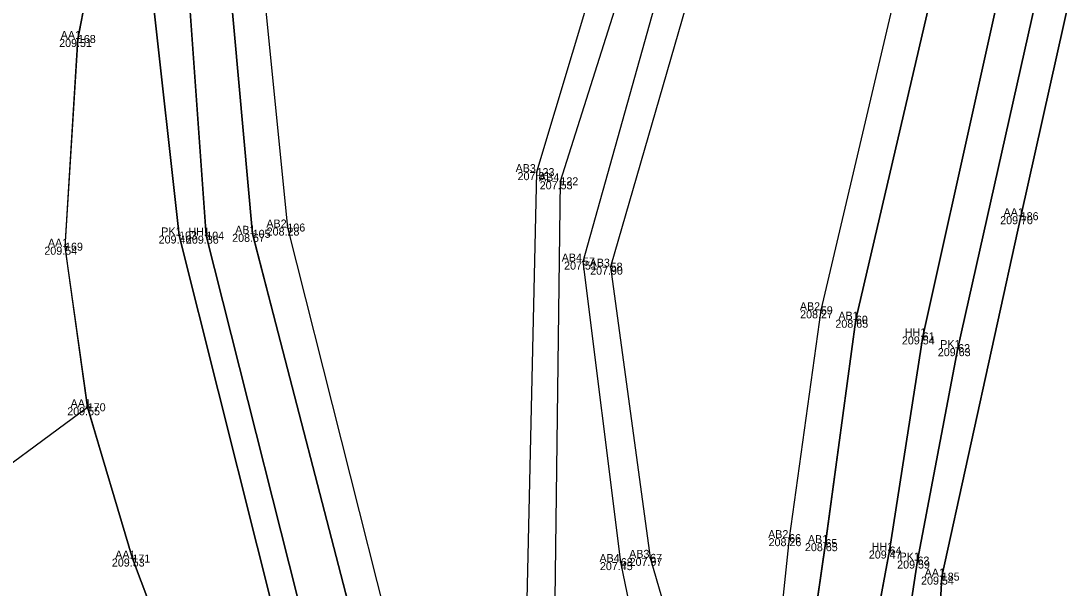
# Model space of a CAD drawing. Extents: x -263091 to -262565, y -1238731 to -1237092.
# Drawn here: x -262957.98 to -262931.8, y -1238381.51 to -1238367.34 of the extents above; entities that cross this region are included whole.
import ezdxf

# ---------------------------------------------------------------- set-up
doc = ezdxf.new("R2010")
doc.units = 0
for name, color, linetype in [('01_Hrana_betónu', 7, 'Continuous'), ('02_Oplotenie', 7, 'Continuous'), ('03_Asfalt', 7, 'Continuous'), ('05_Hrana_terénu', 7, 'Continuous'), ('Groma (21)', 7, 'Continuous'), ('Groma (22)', 7, 'Continuous'), ('Groma (23)', 7, 'Continuous'), ('Groma (24)', 7, 'Continuous'), ('U002_Asfalt', 7, 'Continuous'), ('U002_Betónové panely', 7, 'Continuous'), ('U002_Zeleň_mimo', 7, 'Continuous'), ('U002_Zeleň_vnútro', 7, 'Continuous'), ('U002_Zeleň_zatrávňovač', 7, 'Continuous')]:
    doc.layers.add(name, color=color, linetype=linetype)

msp = doc.modelspace()

# ---------------------------------------------------------------- linework, layer by layer
at = {"layer": '01_Hrana_betónu'}
for points in [[(-262944.213, -1238387.387), (-262944.634, -1238381.789), (-262944.5, -1238371.343), (-262941.2, -1238360.927), (-262935.086, -1238341.218), (-262927.632, -1238317.179), (-262920.793, -1238295.265), (-262911.171, -1238262.813), (-262915.352, -1238261.064), (-262915.337, -1238259.329), (-262909.866, -1238261.629), (-262904.904, -1238263.716)], [(-262916.095, -1238261.519), (-262911.974, -1238263.293), (-262921.591, -1238294.909), (-262928.534, -1238317.073), (-262935.896, -1238340.99), (-262941.971, -1238360.685), (-262945.096, -1238371.115), (-262945.34, -1238381.803), (-262945.412, -1238387.557)], [(-262941.714, -1238387.032), (-262942.991, -1238380.859), (-262943.934, -1238373.35), (-262940.485, -1238361.041), (-262934.456, -1238341.421), (-262927.277, -1238318.134), (-262920.116, -1238294.802), (-262913.64, -1238273.614), (-262910.214, -1238263.245), (-262905.769, -1238265.099), (-262904.904, -1238263.716)], [(-262905.769, -1238265.099), (-262909.81, -1238264.181), (-262912.956, -1238273.861), (-262919.396, -1238295.066), (-262926.538, -1238318.409), (-262933.693, -1238341.579), (-262939.683, -1238361.151), (-262943.246, -1238373.477), (-262942.259, -1238380.752), (-262940.526, -1238386.713)], [(-262905.769, -1238265.099), (-262909.014, -1238275.12), (-262915.393, -1238296.189), (-262922.597, -1238319.497), (-262929.796, -1238342.936), (-262935.083, -1238362.17), (-262937.995, -1238374.567), (-262938.788, -1238380.26), (-262939.46, -1238386.668), (-262940.526, -1238386.713), (-262940.498, -1238386.859)], [(-262940.36, -1238387.407), (-262939.388, -1238387.391), (-262938.822, -1238386.902), (-262937.88, -1238380.385), (-262937.119, -1238374.802), (-262934.23, -1238362.39), (-262928.952, -1238343.2), (-262921.717, -1238319.813), (-262915.107, -1238298.192), (-262908.208, -1238275.423), (-262904.855, -1238265.436)], [(-262945.333, -1238387.95), (-262946.617, -1238387.98), (-262947.712, -1238387.066), (-262949.402, -1238383.422), (-262952.187, -1238372.656), (-262952.759, -1238366.382)], [(-262951.91, -1238366.581), (-262951.321, -1238372.499), (-262948.634, -1238383.126), (-262947.098, -1238386.578), (-262946.426, -1238387.428), (-262945.412, -1238387.557)]]:
    msp.add_lwpolyline(points, dxfattribs=at)
at = {"layer": '02_Oplotenie'}
msp.add_lwpolyline([(-262939.39, -1238320.83), (-262941.19, -1238324.79), (-262946.68, -1238336.9), (-262951.035, -1238350.68), (-262953.195, -1238358.97), (-262953.815, -1238358.809), (-262955.312, -1238364.513), (-262954.553, -1238364.724), (-262954.681, -1238366.785), (-262954.024, -1238372.698), (-262951.104, -1238384.342), (-262949.016, -1238390.045), (-262944.443, -1238389.969), (-262936.906, -1238389.616), (-262935.581, -1238380.82), (-262934.566, -1238375.513), (-262931.812, -1238363.194), (-262926.159, -1238344.076), (-262918.903, -1238320.384), (-262912.242, -1238298.942), (-262905.326, -1238276.054), (-262902.598, -1238266.292), (-262902.107, -1238264.892)], dxfattribs=at)
at = {"layer": '03_Asfalt'}
msp.add_lwpolyline([(-262931.199, -1238364.162), (-262933.003, -1238372.216), (-262934.974, -1238381.221), (-262935.119, -1238384.027), (-262936.052, -1238388.803), (-262936.611, -1238390.144), (-262937.981, -1238391.744), (-262940.017, -1238393.235), (-262941.857, -1238393.766), (-262943.351, -1238393.675), (-262945.246, -1238393.033), (-262947.034, -1238391.969), (-262949.331, -1238390.232), (-262950.782, -1238388.665), (-262952.605, -1238386.269), (-262954.108, -1238383.642), (-262955.193, -1238380.77), (-262956.307, -1238376.99), (-262956.874, -1238372.978), (-262956.554, -1238367.788), (-262955.999, -1238364.917)], dxfattribs=at)
at = {"layer": '05_Hrana_terénu'}
msp.add_lwpolyline([(-262920.126, -1238320.151), (-262927.385, -1238343.686), (-262932.704, -1238362.854), (-262935.453, -1238375.219), (-262936.279, -1238380.57), (-262937.519, -1238387.253), (-262938.314, -1238388.733), (-262939.759, -1238389.403), (-262945.681, -1238389.45), (-262947.587, -1238388.865), (-262949.049, -1238387.288), (-262950.436, -1238384.21), (-262953.347, -1238372.702), (-262953.777, -1238366.63), (-262954.163, -1238366.041), (-262952.487, -1238358.01), (-262951.855, -1238357.25), (-262949.897, -1238349.853), (-262950.29, -1238348.92), (-262949.45, -1238345.83), (-262948.76, -1238345.496), (-262946.63, -1238339.15), (-262945.04, -1238334.12), (-262941.75, -1238326.63)], dxfattribs=at)
at = {"layer": 'Groma (21)'}
for centre in [(-262956.554, -1238367.788), (-262945.096, -1238371.115), (-262944.5, -1238371.343), (-262933.003, -1238372.216), (-262952.187, -1238372.656), (-262951.321, -1238372.499), (-262954.024, -1238372.698), (-262953.347, -1238372.702), (-262956.874, -1238372.978), (-262943.934, -1238373.35), (-262943.246, -1238373.477), (-262937.995, -1238374.567), (-262937.119, -1238374.802), (-262935.453, -1238375.219), (-262934.566, -1238375.513), (-262956.307, -1238376.99), (-262938.788, -1238380.26), (-262937.88, -1238380.385), (-262955.193, -1238380.77), (-262942.259, -1238380.752), (-262936.279, -1238380.57), (-262942.991, -1238380.859), (-262935.581, -1238380.82), (-262934.974, -1238381.221)]:
    msp.add_circle(centre, 0.01, dxfattribs=at)
at = {"layer": 'U002_Asfalt'}
msp.add_lwpolyline([(-262962.63, -1238381.65), (-262956.31, -1238376.99), (-262955.19, -1238380.77), (-262954.11, -1238383.64), (-262952.61, -1238386.27), (-262950.78, -1238388.67), (-262949.33, -1238390.23), (-262947.03, -1238391.97), (-262945.25, -1238393.03), (-262943.35, -1238393.68), (-262941.86, -1238393.77), (-262940.02, -1238393.24), (-262937.98, -1238391.74), (-262936.61, -1238390.14), (-262936.05, -1238388.8), (-262935.12, -1238384.03), (-262934.97, -1238381.22), (-262933, -1238372.22), (-262931.2, -1238364.16)], dxfattribs=at)
msp.add_lwpolyline([(-262962.63, -1238381.65), (-262956.31, -1238376.99), (-262955.19, -1238380.77), (-262954.11, -1238383.64), (-262952.61, -1238386.27), (-262950.78, -1238388.67), (-262949.33, -1238390.23), (-262947.03, -1238391.97), (-262945.25, -1238393.03), (-262943.35, -1238393.68), (-262941.86, -1238393.77), (-262940.02, -1238393.24), (-262937.98, -1238391.74), (-262936.61, -1238390.14), (-262936.05, -1238388.8), (-262935.12, -1238384.03), (-262934.97, -1238381.22), (-262933, -1238372.22), (-262931.2, -1238364.16)], dxfattribs=at)
at = {"layer": 'U002_Betónové panely'}
msp.add_lwpolyline([(-262934.23, -1238362.39), (-262937.12, -1238374.8), (-262937.88, -1238380.39), (-262938.82, -1238386.9), (-262939.39, -1238387.39), (-262940.36, -1238387.41), (-262940.41, -1238387.31), (-262940.5, -1238386.86), (-262941.71, -1238387.03), (-262944.21, -1238387.39), (-262945.41, -1238387.56), (-262945.33, -1238387.95), (-262946.62, -1238387.98), (-262947.71, -1238387.07), (-262949.4, -1238383.42), (-262952.19, -1238372.66), (-262952.76, -1238366.38)], dxfattribs=at)
msp.add_lwpolyline([(-262934.23, -1238362.39), (-262937.12, -1238374.8), (-262937.88, -1238380.39), (-262938.82, -1238386.9), (-262939.39, -1238387.39), (-262940.36, -1238387.41), (-262940.41, -1238387.31), (-262940.5, -1238386.86), (-262941.71, -1238387.03), (-262944.21, -1238387.39), (-262945.41, -1238387.56), (-262945.33, -1238387.95), (-262946.62, -1238387.98), (-262947.71, -1238387.07), (-262949.4, -1238383.42), (-262952.19, -1238372.66), (-262952.76, -1238366.38)], dxfattribs=at)
at = {"layer": 'U002_Zeleň_mimo'}
for points in [[(-262954.68, -1238366.78), (-262954.02, -1238372.7), (-262951.1, -1238384.34), (-262949.02, -1238390.05), (-262944.44, -1238389.97), (-262936.91, -1238389.62), (-262935.58, -1238380.82), (-262934.57, -1238375.51), (-262931.81, -1238363.19)], [(-262931.2, -1238364.16), (-262933, -1238372.22), (-262934.97, -1238381.22), (-262935.12, -1238384.03), (-262936.05, -1238388.8), (-262936.61, -1238390.14), (-262937.98, -1238391.74), (-262940.02, -1238393.24), (-262941.86, -1238393.77), (-262943.35, -1238393.68), (-262945.25, -1238393.03), (-262947.03, -1238391.97), (-262949.33, -1238390.23), (-262950.78, -1238388.67), (-262952.61, -1238386.27), (-262954.11, -1238383.64), (-262955.19, -1238380.77), (-262956.31, -1238376.99), (-262956.87, -1238372.98), (-262956.55, -1238367.79), (-262956, -1238364.92)]]:
    msp.add_lwpolyline(points, dxfattribs=at)
at = {"layer": 'U002_Zeleň_vnútro'}
for points in [[(-262918.9, -1238320.38), (-262926.16, -1238344.08), (-262931.81, -1238363.19), (-262934.57, -1238375.51), (-262935.58, -1238380.82), (-262936.91, -1238389.62), (-262944.44, -1238389.97), (-262949.02, -1238390.05), (-262951.1, -1238384.34), (-262954.02, -1238372.7), (-262954.68, -1238366.78), (-262954.55, -1238364.72), (-262955.31, -1238364.51), (-262953.82, -1238358.81), (-262953.2, -1238358.97), (-262951.03, -1238350.68), (-262946.68, -1238336.9), (-262941.19, -1238324.79)], [(-262918.9, -1238320.38), (-262926.16, -1238344.08), (-262931.81, -1238363.19), (-262934.57, -1238375.51), (-262935.58, -1238380.82), (-262936.91, -1238389.62), (-262944.44, -1238389.97), (-262949.02, -1238390.05)], [(-262949.02, -1238390.05), (-262951.1, -1238384.34), (-262954.02, -1238372.7), (-262954.68, -1238366.78), (-262954.55, -1238364.72), (-262955.31, -1238364.51), (-262953.82, -1238358.81), (-262953.2, -1238358.97), (-262951.03, -1238350.68), (-262946.68, -1238336.9), (-262941.19, -1238324.79)], [(-262953.78, -1238366.63), (-262953.35, -1238372.7), (-262950.44, -1238384.21), (-262949.05, -1238387.29), (-262947.59, -1238388.87), (-262945.68, -1238389.45), (-262939.76, -1238389.4), (-262938.31, -1238388.73), (-262937.52, -1238387.25), (-262936.28, -1238380.57), (-262935.45, -1238375.22), (-262932.7, -1238362.85)], [(-262953.78, -1238366.63), (-262953.35, -1238372.7), (-262950.44, -1238384.21), (-262949.05, -1238387.29), (-262947.59, -1238388.87), (-262945.68, -1238389.45), (-262939.76, -1238389.4), (-262938.31, -1238388.73), (-262937.52, -1238387.25), (-262936.28, -1238380.57), (-262935.45, -1238375.22), (-262932.7, -1238362.85)]]:
    msp.add_lwpolyline(points, dxfattribs=at)
at = {"layer": 'U002_Zeleň_zatrávňovač'}
for points in [[(-262945.68, -1238389.45), (-262947.59, -1238388.87), (-262949.05, -1238387.29), (-262950.44, -1238384.21), (-262953.35, -1238372.7), (-262953.78, -1238366.63), (-262954.16, -1238366.04), (-262952.76, -1238366.38), (-262952.19, -1238372.66), (-262949.4, -1238383.42), (-262947.71, -1238387.07), (-262946.62, -1238387.98), (-262945.33, -1238387.95), (-262940.41, -1238387.31), (-262940.36, -1238387.41), (-262939.39, -1238387.39), (-262938.82, -1238386.9), (-262937.88, -1238380.39), (-262937.12, -1238374.8), (-262934.23, -1238362.39), (-262928.95, -1238343.2), (-262921.72, -1238319.81)], [(-262920.13, -1238320.15), (-262927.39, -1238343.69), (-262932.7, -1238362.85), (-262935.45, -1238375.22), (-262936.28, -1238380.57), (-262937.52, -1238387.25), (-262938.31, -1238388.73), (-262939.76, -1238389.4), (-262945.68, -1238389.45)], [(-262952.76, -1238366.38), (-262952.19, -1238372.66), (-262949.4, -1238383.42), (-262947.71, -1238387.07), (-262946.62, -1238387.98), (-262945.33, -1238387.95), (-262940.41, -1238387.31), (-262940.36, -1238387.41), (-262939.39, -1238387.39), (-262938.82, -1238386.9), (-262937.88, -1238380.39), (-262937.12, -1238374.8), (-262934.23, -1238362.39)], [(-262932.7, -1238362.85), (-262935.45, -1238375.22), (-262936.28, -1238380.57), (-262937.52, -1238387.25), (-262938.31, -1238388.73), (-262939.76, -1238389.4), (-262945.68, -1238389.45), (-262947.59, -1238388.87), (-262949.05, -1238387.29), (-262950.44, -1238384.21), (-262953.35, -1238372.7), (-262953.78, -1238366.63)]]:
    msp.add_lwpolyline(points, dxfattribs=at)

# ---------------------------------------------------------------- texts
at = {"layer": 'Groma (22)'}
for s, p in [('168', (-262956.554, -1238367.888)), ('123', (-262945.096, -1238371.215)), ('122', (-262944.5, -1238371.443)), ('186', (-262933.003, -1238372.316)), ('103', (-262954.024, -1238372.798)), ('104', (-262953.347, -1238372.802)), ('105', (-262952.187, -1238372.756)), ('106', (-262951.321, -1238372.599)), ('169', (-262956.874, -1238373.078)), ('57', (-262943.934, -1238373.45)), ('58', (-262943.246, -1238373.577)), ('59', (-262937.995, -1238374.667)), ('60', (-262937.119, -1238374.902)), ('61', (-262935.453, -1238375.319)), ('62', (-262934.566, -1238375.613)), ('170', (-262956.307, -1238377.09)), ('66', (-262938.788, -1238380.36)), ('65', (-262937.88, -1238380.485)), ('64', (-262936.279, -1238380.67)), ('171', (-262955.193, -1238380.87)), ('68', (-262942.991, -1238380.959)), ('67', (-262942.259, -1238380.852)), ('63', (-262935.581, -1238380.92)), ('185', (-262934.974, -1238381.321))]:
    msp.add_text(s, height=0.2, dxfattribs=at).set_placement(p)
at = {"layer": 'Groma (23)'}
for s, p in [('209.51', (-262957.022, -1238367.988)), ('207.81', (-262945.57, -1238371.315)), ('207.53', (-262945.017, -1238371.543)), ('209.70', (-262933.515, -1238372.416)), ('208.28', (-262951.838, -1238372.699)), ('209.46', (-262954.536, -1238372.898)), ('209.36', (-262953.854, -1238372.902)), ('208.67', (-262952.7, -1238372.856)), ('209.54', (-262957.391, -1238373.178)), ('207.51', (-262944.408, -1238373.55)), ('207.90', (-262943.758, -1238373.677)), ('208.27', (-262938.512, -1238374.767)), ('208.65', (-262937.631, -1238375.002)), ('209.54', (-262935.97, -1238375.419)), ('209.63', (-262935.073, -1238375.713)), ('209.55', (-262956.819, -1238377.19)), ('208.26', (-262939.3, -1238380.46)), ('208.65', (-262938.392, -1238380.585)), ('207.97', (-262942.772, -1238380.952)), ('209.47', (-262936.796, -1238380.77)), ('209.53', (-262955.705, -1238380.97)), ('207.45', (-262943.513, -1238381.059)), ('209.59', (-262936.088, -1238381.02)), ('209.54', (-262935.491, -1238381.421))]:
    msp.add_text(s, height=0.2, dxfattribs=at).set_placement(p)
at = {"layer": 'Groma (24)'}
for s, p in [('AA1', (-262956.982, -1238367.788)), ('AB3', (-262945.62, -1238371.115)), ('AB4', (-262945.034, -1238371.343)), ('AA1', (-262933.431, -1238372.216)), ('AB2', (-262951.845, -1238372.499)), ('PK1', (-262954.471, -1238372.698)), ('HH1', (-262953.794, -1238372.702)), ('AB1', (-262952.625, -1238372.656)), ('AA1', (-262957.302, -1238372.978)), ('AB4', (-262944.468, -1238373.35)), ('AB3', (-262943.77, -1238373.477)), ('AB2', (-262938.519, -1238374.567)), ('AB1', (-262937.557, -1238374.802)), ('HH1', (-262935.9, -1238375.219)), ('PK1', (-262935.013, -1238375.513)), ('AA1', (-262956.735, -1238376.99)), ('AB2', (-262939.312, -1238380.26)), ('AB1', (-262938.318, -1238380.385)), ('HH1', (-262936.726, -1238380.57)), ('AA1', (-262955.621, -1238380.77)), ('AB4', (-262943.525, -1238380.859)), ('AB3', (-262942.783, -1238380.752)), ('PK1', (-262936.028, -1238380.82)), ('AA1', (-262935.402, -1238381.221))]:
    msp.add_text(s, height=0.2, dxfattribs=at).set_placement(p)

doc.saveas('drawing.dxf')
